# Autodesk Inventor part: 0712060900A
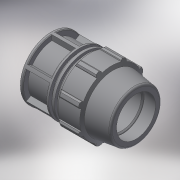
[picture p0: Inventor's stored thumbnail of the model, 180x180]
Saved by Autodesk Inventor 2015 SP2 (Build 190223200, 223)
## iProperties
Created: 2017-02
Part Number: 0712060900A
Material: Generic
Description: PLASSON END PLUG 90
Document SubType Name: Modeling
Designer: KIM
Mass: 947.017 g
Surface Area: 1382.98 cm^2
Volume: 947.017 cm^3
Density: 1 g/cm^3
Appearance: Default
Author: Кирилл
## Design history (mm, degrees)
derived "87120.ipt"
feature "Solid1::87120.ipt"
tag "TaggingFeature1"
body "Solid1"
other parameters: "d4" = 30.28571, "d5" = 53, "d7" = 154, "d8" = 115.5, "d9" = 30.28571, "d11" = 6.05714, "d12" = 123.2, "d13" = 120 deg, "d14" = 117, "d15" = 8 deg, "d16" = 138.6, "d18" = 4.5, "d19" = 35 deg, "d20" = 17.5 deg, "d21" = 143.22, "d23" = 0, "d25" = 360 deg, "d27" = 3.08, "d34" = 7.7, "d36" = 0, "d42" = 53, "d43" = 4.62, "d46" = 2.7, "d53" = 1.8, "d55" = 360 deg, "d59" = 53, "d64" = 212, "d66" = 20.02, "d67" = 12.32, "d70" = 24.22857, "d71" = 6.05714, "d72" = 135.828, "d75" = 12.11429, "E_" = 154, "H_" = 212
